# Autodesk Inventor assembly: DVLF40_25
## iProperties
Created: 2010-03
Part Number: DVLF40_25
Document SubType Name: Assembly
Designer: TB
Mass: 478.969 g
Surface Area: 1100.56 cm^2
Volume: 478.969 cm^3
Density: 1 g/cm^3
Description: KM DVLF 40/25 - 100 mm
Slaglengde: 100.000 mm
Author: TB
